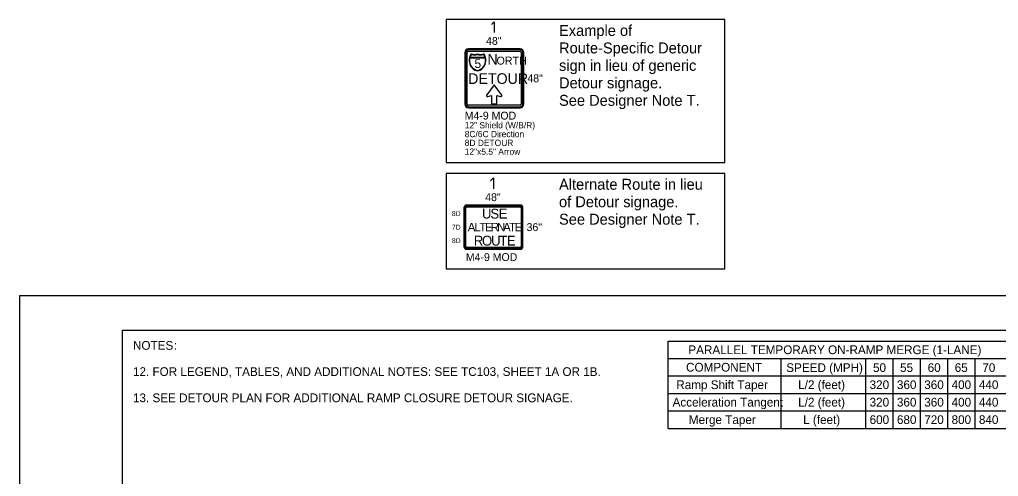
# Model space of a CAD drawing. Extents: x 99999 to 100116, y 99995 to 100013.
# Drawn here: x 100059.06 to 100068.02, y 100009.03 to 100013.22 of the extents above; entities that cross this region are included whole.
import ezdxf

# ---------------------------------------------------------------- set-up
doc = ezdxf.new("R2010")
doc.units = 0
for name, color, linetype in [('SH_GI_GeneralNotesBodyText', 7, 'Continuous'), ('SH_GI_PlotLimits', 7, 'Continuous'), ('SH_GI_SheetBorder', 7, 'Continuous'), ('SH_TI_Tables', 7, 'Continuous'), ('TR_SN_ConstructionSigns', 7, 'Continuous'), ('TR_WZ_WorkZoneDetails', 7, 'Continuous')]:
    doc.layers.add(name, color=color, linetype=linetype)

msp = doc.modelspace()

# ---------------------------------------------------------------- linework, layer by layer
at = {"layer": 'SH_GI_PlotLimits'}
msp.add_lwpolyline([(100059.0625, 99999.6875), (100076.0625, 99999.6875), (100076.0625, 100010.6875), (100059.0625, 100010.6875)], close=True, dxfattribs=at)
at = {"layer": 'SH_GI_SheetBorder'}
for q in [(100060, 100000), (100075.75, 100010.375)]:
    msp.add_line((100060, 100010.375), q, dxfattribs=at)
at = {"layer": 'SH_TI_Tables'}
for p, q in [((100064.9972, 100010.275), (100068.3028, 100010.275)), ((100064.9972, 100009.475), (100064.9972, 100010.275)), ((100064.9972, 100010.115), (100068.3028, 100010.115)), ((100066.0286, 100010.115), (100066.0286, 100009.795)), ((100066.8028, 100010.115), (100066.8028, 100009.795)), ((100067.0528, 100010.115), (100067.0528, 100009.795)), ((100067.3028, 100010.115), (100067.3028, 100009.795)), ((100067.5528, 100010.115), (100067.5528, 100009.795)), ((100067.8028, 100010.115), (100067.8028, 100009.795)), ((100064.9972, 100009.955), (100066.8028, 100009.955)), ((100066.8028, 100009.955), (100068.3028, 100009.955)), ((100064.9972, 100009.795), (100066.8028, 100009.795)), ((100066.0286, 100009.795), (100066.0286, 100009.635)), ((100066.8028, 100009.795), (100068.3028, 100009.795)), ((100066.8028, 100009.795), (100066.8028, 100009.635)), ((100067.0528, 100009.795), (100067.0528, 100009.635)), ((100067.3028, 100009.795), (100067.3028, 100009.635)), ((100067.5528, 100009.795), (100067.5528, 100009.635)), ((100067.8028, 100009.795), (100067.8028, 100009.635)), ((100064.9972, 100009.635), (100066.8028, 100009.635)), ((100066.0286, 100009.635), (100066.0286, 100009.475)), ((100066.8028, 100009.635), (100068.3028, 100009.635)), ((100066.8028, 100009.635), (100066.8028, 100009.475)), ((100067.0528, 100009.635), (100067.0528, 100009.475)), ((100067.3028, 100009.635), (100067.3028, 100009.475)), ((100067.5528, 100009.635), (100067.5528, 100009.475)), ((100067.8028, 100009.635), (100067.8028, 100009.475)), ((100064.9972, 100009.475), (100066.8028, 100009.475)), ((100066.8028, 100009.475), (100068.3028, 100009.475))]:
    msp.add_line(p, q, dxfattribs=at)
at = {"layer": 'TR_SN_ConstructionSigns'}
for p, q in [((100063.1354, 100012.9173), (100063.1354, 100012.4448)), ((100063.1438, 100012.9173), (100063.1438, 100012.4448)), ((100063.1579, 100012.4448), (100063.1579, 100012.9173)), ((100063.6416, 100012.9511), (100063.1691, 100012.9511)), ((100063.6416, 100012.9426), (100063.1691, 100012.9426)), ((100063.1691, 100012.9286), (100063.6416, 100012.9286)), ((100063.6529, 100012.9173), (100063.6529, 100012.4448)), ((100063.6669, 100012.4448), (100063.6669, 100012.9173)), ((100063.6754, 100012.4448), (100063.6754, 100012.9173)), ((100063.3228, 100012.8675), (100063.1823, 100012.8675)), ((100063.1823, 100012.8675), (100063.3228, 100012.8675)), ((100063.1834, 100012.8712), (100063.3217, 100012.8712)), ((100063.3217, 100012.8712), (100063.1834, 100012.8712)), ((100063.6416, 100012.4336), (100063.1691, 100012.4336)), ((100063.1691, 100012.4195), (100063.6416, 100012.4195)), ((100063.1691, 100012.4111), (100063.6416, 100012.4111)), ((100063.1277, 100011.4952), (100063.1277, 100011.1408)), ((100063.1347, 100011.4952), (100063.1347, 100011.1408)), ((100063.1446, 100011.1408), (100063.1446, 100011.4952)), ((100063.6424, 100011.5205), (100063.153, 100011.5205)), ((100063.6424, 100011.5135), (100063.153, 100011.5135)), ((100063.153, 100011.5036), (100063.6424, 100011.5036)), ((100063.6508, 100011.4952), (100063.6508, 100011.1408)), ((100063.6607, 100011.1408), (100063.6607, 100011.4952)), ((100063.6677, 100011.1408), (100063.6677, 100011.4952)), ((100063.6424, 100011.1324), (100063.153, 100011.1324)), ((100063.153, 100011.1225), (100063.6424, 100011.1225)), ((100063.153, 100011.1155), (100063.6424, 100011.1155))]:
    msp.add_line(p, q, dxfattribs=at)
msp.add_lwpolyline([(100063.3367, 100012.5294), (100063.3356, 100012.5278), (100063.335, 100012.5261), (100063.3347, 100012.5241), (100063.3348, 100012.5224), (100063.335, 100012.5212), (100063.3356, 100012.5198), (100063.3373, 100012.5175), (100063.3386, 100012.5164), (100063.34, 100012.5155), (100063.3417, 100012.5148), (100063.3432, 100012.5145), (100063.3447, 100012.5143), (100063.3465, 100012.5143), (100063.3478, 100012.5146), (100063.3795, 100012.5224), (100063.3795, 100012.4471), (100063.4307, 100012.4471), (100063.4307, 100012.5229), (100063.4617, 100012.5137), (100063.4647, 100012.5131), (100063.4681, 100012.5134), (100063.4703, 100012.5142), (100063.4733, 100012.5162), (100063.4752, 100012.5189), (100063.476, 100012.5214), (100063.4761, 100012.5236), (100063.4754, 100012.5263), (100063.4746, 100012.5277), (100063.4051, 100012.6205), (100063.3367, 100012.5294)], dxfattribs=at)
for centre, radius, start, end in [((100063.1691, 100012.9173), 0.0337, 90, 180), ((100063.1691, 100012.9173), 0.0253, 90, 180), ((100063.1691, 100012.9173), 0.0113, 90, 180), ((100063.6416, 100012.9173), 0.0338, 360, 90), ((100063.6416, 100012.9173), 0.0253, 360, 90), ((100063.6416, 100012.9173), 0.0113, 360, 90), ((100063.2725, 100012.8442), 0.0973, 142.16169, 258.18105), ((100063.2715, 100012.8433), 0.0925, 164.85517, 258.18105), ((100063.2715, 100012.8433), 0.0925, 164.85517, 258.18105), ((100063.2715, 100012.8433), 0.0925, 142.16169, 162.48397), ((100063.2715, 100012.8433), 0.0925, 142.16169, 162.48397), ((100063.2245, 100013.0012), 0.1014, 253.48525, 286.04538), ((100063.2259, 100012.9924), 0.0964, 253.48525, 286.04538), ((100063.2259, 100012.9924), 0.0964, 253.48525, 286.04538), ((100063.2806, 100013.0012), 0.1014, 253.95462, 286.51475), ((100063.2792, 100012.9924), 0.0964, 253.95462, 286.51475), ((100063.2792, 100012.9924), 0.0964, 253.95462, 286.51475), ((100063.2325, 100012.8442), 0.0974, 281.90384, 37.84925), ((100063.2335, 100012.8433), 0.0925, 281.90384, 15.1558), ((100063.2335, 100012.8433), 0.0925, 281.90384, 15.1558), ((100063.2335, 100012.8433), 0.0925, 17.52691, 37.84925), ((100063.2335, 100012.8433), 0.0925, 17.52691, 37.84925), ((100063.1691, 100012.4448), 0.0338, 180, 270), ((100063.1691, 100012.4448), 0.0253, 180, 270), ((100063.1691, 100012.4448), 0.0113, 180, 270), ((100063.6416, 100012.4448), 0.0337, 270, 360), ((100063.6416, 100012.4448), 0.0253, 270, 0), ((100063.6416, 100012.4448), 0.0113, 270, 0), ((100063.153, 100011.4952), 0.0253, 90, 180), ((100063.153, 100011.4952), 0.0183, 90, 180), ((100063.153, 100011.4952), 0.00844, 90, 180), ((100063.6424, 100011.4952), 0.0253, 360, 90), ((100063.6424, 100011.4952), 0.0183, 360, 90), ((100063.6424, 100011.4952), 0.00844, 360, 90), ((100063.153, 100011.1408), 0.0253, 180, 270), ((100063.153, 100011.1408), 0.0183, 180, 270), ((100063.153, 100011.1408), 0.00844, 180, 270), ((100063.6424, 100011.1408), 0.0253, 270, 360), ((100063.6424, 100011.1408), 0.0183, 270, 0), ((100063.6424, 100011.1408), 0.00844, 270, 0)]:
    msp.add_arc(centre, radius, start, end, dxfattribs=at)
at = {"layer": 'TR_WZ_WorkZoneDetails'}
for p, q in [((100063.3804, 100013.1741), (100063.4054, 100013.1991)), ((100063.4054, 100013.1991), (100063.4054, 100013.0991)), ((100063.3727, 100011.7435), (100063.3977, 100011.7685)), ((100063.3977, 100011.7685), (100063.3977, 100011.6685))]:
    msp.add_line(p, q, dxfattribs=at)
for points in [[(100062.9666, 100011.9105), (100065.5143, 100011.9105), (100065.5143, 100013.2191), (100062.9666, 100013.2191)], [(100062.9666, 100010.9375), (100065.5143, 100010.9375), (100065.5143, 100011.8105), (100062.9666, 100011.8105)]]:
    msp.add_lwpolyline(points, close=True, dxfattribs=at)

# ---------------------------------------------------------------- texts
at = {"layer": 'SH_GI_GeneralNotesBodyText'}
for s, p in [('NOTES', (100060.1, 100010.195)), (':', (100060.4743, 100010.195)), ('12. FOR LEGEND, TABLES, AND ADDITIONAL NOTES: SEE TC103, SHEET 1A OR 1B.', (100060.1, 100009.955)), ('13. SEE DETOUR PLAN FOR ADDITIONAL RAMP CLOSURE DETOUR SIGNAGE.', (100060.1, 100009.715))]:
    msp.add_text(s, height=0.08, rotation=360, dxfattribs=at).set_placement(p)
at = {"layer": 'SH_TI_Tables'}
for s, p in [('PARALLEL TEMPORARY ON-RAMP MERGE (1-LANE)', (100065.1817, 100010.155)), ('COMPONENT', (100065.1605, 100009.995)), ('SPEED (MPH)', (100066.0775, 100009.9915)), ('50', (100066.8712, 100009.9915)), ('55', (100067.1187, 100009.9915)), ('60', (100067.3712, 100009.9915)), ('65', (100067.6187, 100009.9915)), ('70', (100067.8712, 100009.9915)), ('Ramp Shift Taper', (100065.0713, 100009.835)), ('L/2 (feet)', (100066.1866, 100009.835)), ('320', (100066.84, 100009.835)), ('360', (100067.09, 100009.835)), ('360', (100067.34, 100009.835)), ('400', (100067.59, 100009.835)), ('440', (100067.84, 100009.835)), ('Acceleration Tangent', (100065.0372, 100009.675)), ('L/2 (feet)', (100066.1866, 100009.675)), ('320', (100066.84, 100009.675)), ('360', (100067.09, 100009.675)), ('360', (100067.34, 100009.675)), ('400', (100067.59, 100009.675)), ('440', (100067.84, 100009.675)), ('Merge Taper', (100065.186, 100009.515)), ('L (feet)', (100066.232, 100009.515)), ('600', (100066.84, 100009.515)), ('680', (100067.09, 100009.515)), ('720', (100067.34, 100009.515)), ('800', (100067.59, 100009.515)), ('840', (100067.84, 100009.515))]:
    msp.add_text(s, height=0.08, rotation=360, dxfattribs=at).set_placement(p)
at = {"layer": 'TR_SN_ConstructionSigns'}
for s, height, p in [('48"', 0.072, (100063.3306, 100012.9871)), ('5', 0.081, (100063.2253, 100012.7751)), ('N', 0.0972, (100063.3432, 100012.8067)), ('ORTH', 0.0729, (100063.4264, 100012.8067)), ('DETOUR', 0.0972, (100063.1668, 100012.6297)), ('48"', 0.072, (100063.7086, 100012.6451)), ('M4-9 MOD', 0.072, (100063.1354, 100012.3031)), ('12" Shield (W/B/R)', 0.0576, (100063.1354, 100012.2224)), ('8C/6C Direction', 0.0576, (100063.1354, 100012.1418)), ('8D DETOUR', 0.0576, (100063.1354, 100012.0611)), ('12"x5.5" Arrow', 0.0576, (100063.1354, 100011.9805)), ('48"', 0.072, (100063.323, 100011.5565)), ('36"', 0.072, (100063.7015, 100011.282)), ('M4-9 MOD', 0.072, (100063.1457, 100011.0075))]:
    msp.add_text(s, height=height, rotation=360, dxfattribs=at).set_placement(p)
for s, height, p in [('U', 0.09, (100063.2933, 100011.3967)), ('S', 0.09, (100063.3698, 100011.3967)), ('E', 0.09, (100063.4463, 100011.3967)), ('8D', 0.045, (100063.018, 100011.4192)), ('7D', 0.045, (100063.018, 100011.2955)), ('A', 0.0787, (100063.1626, 100011.2786)), ('L', 0.0787, (100063.2241, 100011.2786)), ('T', 0.0787, (100063.269, 100011.2786)), ('E', 0.0787, (100063.3201, 100011.2786)), ('R', 0.0787, (100063.3737, 100011.2786)), ('N', 0.0787, (100063.4312, 100011.2786)), ('A', 0.0787, (100063.4863, 100011.2786)), ('T', 0.0787, (100063.5414, 100011.2786)), ('E', 0.0787, (100063.5926, 100011.2786)), ('8D', 0.045, (100063.018, 100011.1717)), ('R', 0.09, (100063.2186, 100011.1492)), ('O', 0.09, (100063.2933, 100011.1492)), ('U', 0.09, (100063.377, 100011.1492)), ('T', 0.09, (100063.4517, 100011.1492)), ('E', 0.09, (100063.521, 100011.1492))]:
    msp.add_text(s, height=height, dxfattribs=at).set_placement(p)
at = {"layer": 'TR_WZ_WorkZoneDetails'}
for s, p in [('Example of ', (100063.9983, 100013.0691)), ('Route-Specific Detour ', (100063.9983, 100012.9091)), ('sign in lieu of generic ', (100063.9983, 100012.7491)), ('Detour signage.', (100063.9983, 100012.5891)), ('See Designer Note T.', (100063.9983, 100012.4291)), ('Alternate Route in lieu ', (100063.9983, 100011.6605)), ('of Detour signage.', (100063.9983, 100011.5005)), ('See Designer Note T.', (100063.9983, 100011.3405))]:
    msp.add_text(s, height=0.1, dxfattribs=at).set_placement(p)

doc.saveas('drawing.dxf')
